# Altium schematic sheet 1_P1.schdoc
size 307 x 218 mm; Symbol: Drawing-Symbol_A4; Device: Drawing-Symbol_A4; Company: 嘉立创EDA; Version: V1.0; Page Size: A4; @Project Name: SKY13575-639LF射频开关1to4; @Page Count: 1; @Update Date: 2025-12-01; @Create Date: 2025-12-01; @Schematic Name: Schematic1; @Page No: 1; @Page Name: P1; @Board Name: Board1; @Create Time: 03:11:56; @Update Time: 11:11:56; Title Block Position: 3; Size: A4; Width: 1170; Height: 825; Region Start: 1; X Region Count: 6; Y Region Count: 4; Blade Width: 10
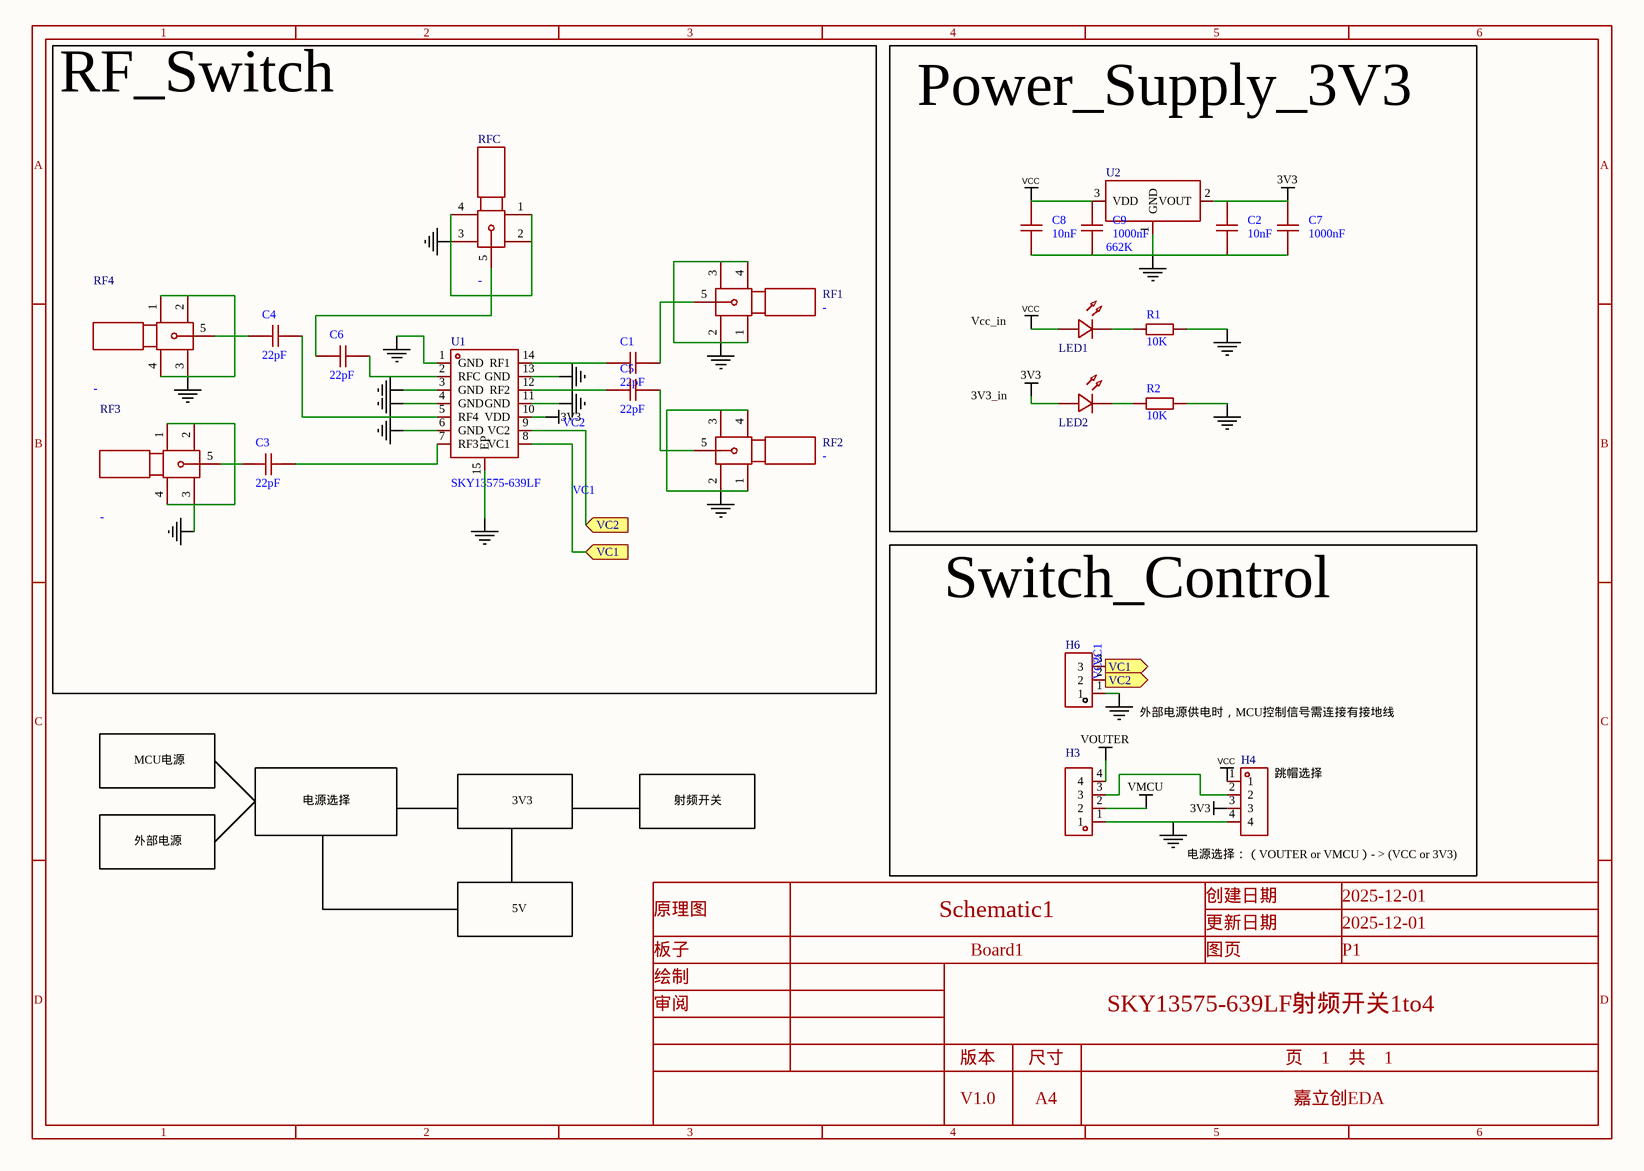
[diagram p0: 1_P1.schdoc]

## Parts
C1  22pF  [C0603]
C2  10nF  [C0603]
C3  22pF  [C0603]
C4  22pF  [C0603]
C5  22pF  [C0603]
C6  22pF  [C0603]
C7  1000nF  [C0603]
C8  10nF  [C0603]
C9  1000nF  [C0603]
H3  (no value)  [HDR-TH_4P-P2.54-V-F]
H4  (no value)  [HDR-TH_4P-P2.54-V-F]
H6  (no value)  [HDR-TH_3P-P2.54-V-F]
LED1  (no value)  [LED_0603]
LED2  (no value)  [LED_0603]
R1  10K  [R0603]
R2  10K  [R0603]
RF1  -  [SMA-SMD_BWSMA-KE-P001]
RF2  -  [SMA-SMD_BWSMA-KE-P001]
RF3  -  [SMA-SMD_BWSMA-KE-P001]
RF4  -  [SMA-SMD_BWSMA-KE-P001]
RFC  -  [SMA-SMD_BWSMA-KE-P001]
U1  SKY13575-639LF  [QFN-14_L1.6-W1.6-P0.40-BL-EP0.7]
U2  662K  [SOT-23-3_L2.9-W1.3-P1.90-LS2.4-BR]

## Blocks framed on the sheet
RF_Switch: C1 C3-C6 RF1-RF4 RFC U1
Power_Supply_3V3: C2 C7-C9 LED1 LED2 R1 R2 U2
Switch_Control: H3 H4 H6

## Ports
VC1 (in), VC1 (out), VC2 (in), VC2 (out)

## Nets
3V3: C2.2 C7.2 H4.3 LED2.2(A) U1.10(VDD) U2.2(VOUT)
GND: C2.1 C7.1 C8.1 C9.1 H3.1 H4.4 H6.1 R1.2 R2.2 RF1.1 RF1.2 RF1.3 RF1.4 RF2.1 RF2.2 RF2.3 RF2.4 RF3.1 RF3.2 RF3.3 RF3.4 RF4.1 RF4.2 RF4.3 RF4.4 RFC.1 RFC.2 RFC.3 RFC.4 U1.1(GND) U1.3(GND) U1.4(GND) U1.6(GND) U1.11(GND) U1.13(GND) U1.15(EP) U2.1(GND)
VCC: C8.2 C9.2 H4.1 LED1.2(A) U2.3(VDD)
VMCU: H3.2
VOUTER: H3.4
VC1: H6.3 U1.8(VC1) ; port VC1
VC2: H6.2 U1.9(VC2) ; port VC2
NetC1_1: C1.1 U1.14(RF1)
NetC1_2: C1.2 RF1.5
NetC3_1: C3.1 RF3.5
NetC3_2: C3.2 U1.7(RF3)
NetC4_1: C4.1 RF4.5
NetC4_2: C4.2 U1.5(RF4)
NetC5_1: C5.1 U1.12(RF2)
NetC5_2: C5.2 RF2.5
NetC6_1: C6.1 RFC.5
NetC6_2: C6.2 U1.2(RFC)
NetH3_3: H3.3 H4.2
NetLED1_1: LED1.1(C) R1.1
NetLED2_1: LED2.1(C) R2.1

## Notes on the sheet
- Vcc_in
- 3V3_in
- 外部电源供电时，MCU控制信号需连接有接地线
- MCU电源
- (near H4) 跳帽选择
- 外部电源
- 电源选择
- 3V3
- 射频开关
- 5V
- (near H4) 电源选择：（VOUTER or VMCU）- > (VCC or 3V3)

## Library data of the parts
C1-C9 = CAP_0603: Symbol: Capacitance; Convert to PCB: yes
H3 H4 = HDR-F_2.54_1x4P: Symbol: 2.54-1*4P母; Convert to PCB: yes
H6 = HDR-F_2.54_1x3P: Symbol: PM254V-11-03-H85; Convert to PCB: yes
LED1 LED2 = LED_0603-R: Symbol: LED_R; Convert to PCB: yes
R1 R2 = Res_0603: Symbol: 电阻; Convert to PCB: yes
RF1-RF4 RFC = BWSMA-KE-P001: Manufacturer: BAT WIRELESS(蝙蝠无线); Add into BOM: yes; Connector Type: 板端; Interface: 内孔; Number of Ports: 1; Interface Diameter: 5.2mm; RF Series: SMA; Impedance: 50Ω; Style: 偏脚
U1 = SKY13575-639LF: Manufacturer: SKYWORKS; Add into BOM: yes
U2 = 662K: Manufacturer: HXY MOSFET(华轩阳电子); Add into BOM: yes; Output Type: 固定; Voltage - Supply: 8V; Output Voltage: 3.3V; Output Current: 300mA; Power Supply Rejection Ratio (PSRR): 40dB@(1kHz); Voltage Dropout: 160mV@(50mA); standby current: 3uA; Output Configuration: 正极; Number of Outputs: 1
